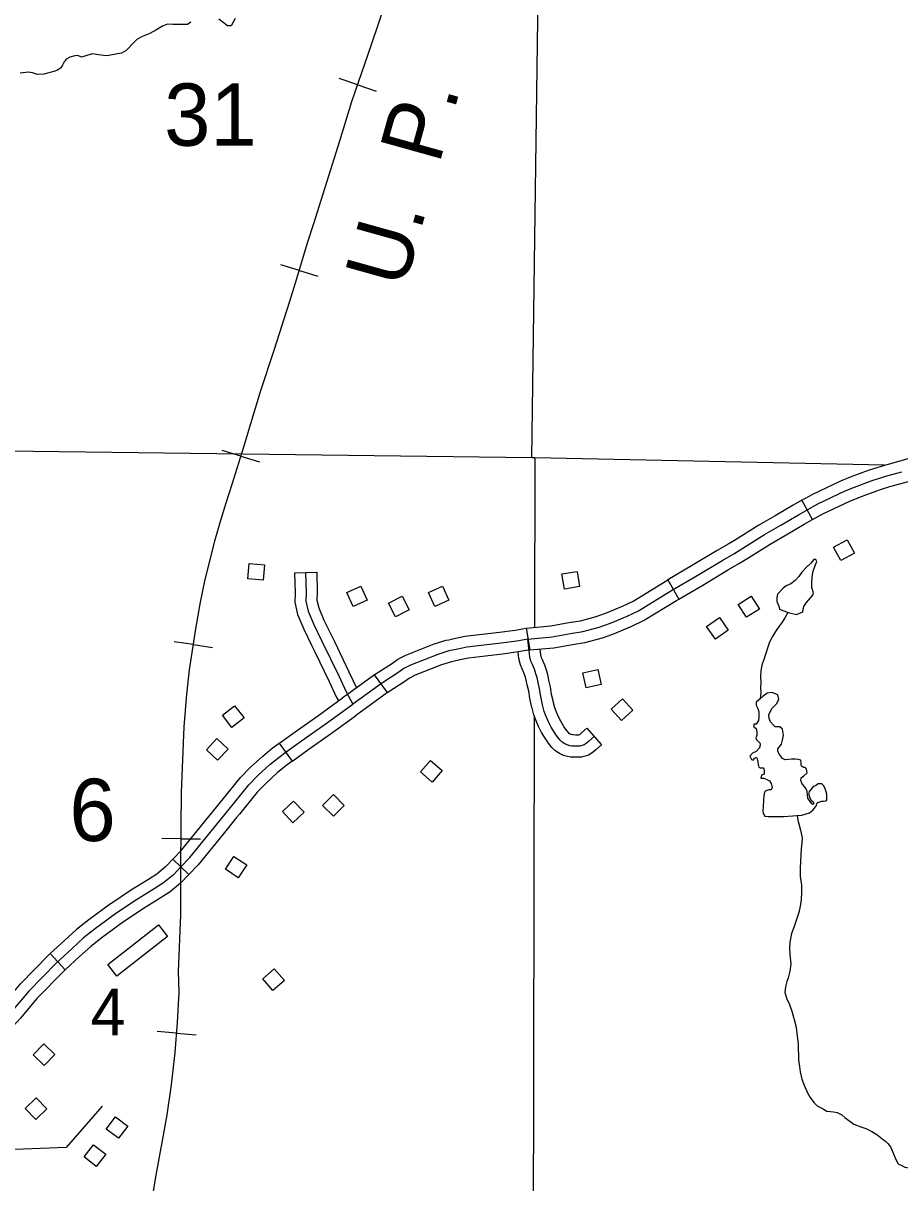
# Model space of a CAD drawing. Extents: x 61396 to 64680, y 55472 to 57605.
# Drawn here: x 62013.4 to 62199.2, y 56228.4 to 56474.2 of the extents above; entities that cross this region are included whole.
import ezdxf

# ---------------------------------------------------------------- set-up
doc = ezdxf.new("R2010")
doc.units = 0
for name, color, linetype in [('31', 7, 'Continuous'), ('35', 7, 'Continuous'), ('4', 7, 'Continuous'), ('40', 7, 'Continuous'), ('45', 7, 'Continuous'), ('5', 7, 'Continuous'), ('56', 7, 'Continuous')]:
    doc.layers.add(name, color=color, linetype=linetype)

msp = doc.modelspace()

# ---------------------------------------------------------------- linework, layer by layer
at = {"layer": '31'}
for p, q in [((62180.65, 56368.97), (62178.38, 56373.08)), ((62178.38, 56373.08), (62178.38, 56373.08)), ((62149.97, 56356.21), (62152.31, 56352.15)), ((62119.96, 56345.97), (62120.77, 56341.36)), ((62090.62, 56332.32), (62087.87, 56336.11)), ((62067.65, 56321.57), (62070.38, 56317.76)), ((62048.53, 56293.76), (62045.15, 56297)), ((62019.17, 56277.06), (62022.34, 56273.6))]:
    msp.add_line(p, q, dxfattribs=at)
for points in [[(62193.89, 56379.89), (62195.74, 56380.47), (62198.96, 56381.37), (62203.46, 56382.62), (62207.07, 56383.35), (62210.22, 56383.87)], [(62120.36, 56343.67), (62125.53, 56344.14), (62129.39, 56344.85), (62131.97, 56345.24), (62135.49, 56346.19), (62137.88, 56347.02), (62141.4, 56348.52), (62143.76, 56349.65), (62150.62, 56353.88), (62156.22, 56357.13), (62161.67, 56360.4), (62164, 56361.75), (62170.47, 56365.79), (62173.93, 56367.78), (62177.69, 56370.02), (62181.8, 56372.29), (62187.59, 56375.04), (62189.58, 56375.87), (62193.28, 56377.25), (62196.41, 56378.23), (62199.59, 56379.12)], [(62178.38, 56373.08), (62180.73, 56374.37), (62186.63, 56377.18), (62188.72, 56378.05), (62192.52, 56379.47), (62193.89, 56379.89)], [(62195.29, 56375.42), (62197.07, 56375.98), (62200.22, 56376.86), (62204.55, 56378.06), (62207.92, 56378.74), (62210.98, 56379.24)], [(62180.65, 56368.97), (62182.87, 56370.2), (62188.54, 56372.9), (62190.44, 56373.69), (62194.04, 56375.03), (62195.29, 56375.42)], [(62178.38, 56373.08), (62176.53, 56372.05), (62172.74, 56369.81), (62169.26, 56367.8), (62164.1, 56364.57)], [(62166.58, 56360.6), (62171.67, 56363.78), (62175.11, 56365.76), (62178.86, 56367.99), (62180.65, 56368.97)], [(62164.1, 56364.57), (62162.79, 56363.76), (62160.48, 56362.42), (62155.03, 56359.15), (62149.97, 56356.21)], [(62152.31, 56352.15), (62157.41, 56355.11), (62162.87, 56358.38), (62165.21, 56359.74), (62166.58, 56360.6)], [(62135.79, 56348.78), (62137.03, 56349.21), (62140.43, 56350.66), (62142.63, 56351.71), (62149.42, 56355.89), (62149.97, 56356.21)], [(62137.33, 56344.35), (62138.72, 56344.83), (62142.37, 56346.39), (62144.88, 56347.59), (62151.82, 56351.87), (62152.31, 56352.15)], [(62119.96, 56345.97), (62125.21, 56346.47), (62129, 56347.16), (62131.48, 56347.54), (62134.8, 56348.44), (62135.79, 56348.78)], [(62103.57, 56343.53), (62105.02, 56343.83), (62107.02, 56344.25), (62114.36, 56345.12), (62117.64, 56345.57), (62119.96, 56345.97)], [(62120.36, 56343.67), (62118, 56343.25), (62114.66, 56342.79), (62107.4, 56341.94), (62105.5, 56341.54), (62103.6, 56341.14), (62101.24, 56340.41), (62095.49, 56338.14), (62094.05, 56337.4), (62092.98, 56336.64), (62089.33, 56334.28), (62083.27, 56329.88)], [(62087.87, 56336.11), (62088, 56336.21), (62091.66, 56338.58), (62092.83, 56339.41), (62094.52, 56340.28), (62100.47, 56342.62), (62103.01, 56343.41), (62103.57, 56343.53)], [(62120.77, 56341.36), (62125.85, 56341.82), (62129.78, 56342.54), (62132.45, 56342.95), (62136.18, 56343.95), (62137.33, 56344.35)], [(62120.77, 56341.36), (62118.36, 56340.94), (62114.96, 56340.47), (62107.78, 56339.62), (62105.98, 56339.25), (62104.53, 56338.94)], [(62104.53, 56338.94), (62104.19, 56338.87), (62102.02, 56338.19), (62096.45, 56336), (62095.27, 56335.4), (62094.29, 56334.7), (62090.66, 56332.35), (62090.62, 56332.32)], [(62087.87, 56336.11), (62081.89, 56331.77), (62081.06, 56331.18)], [(62067.65, 56321.57), (62067.79, 56321.67), (62071.01, 56323.99), (62076.03, 56327.56), (62081.06, 56331.18)], [(62090.62, 56332.32), (62084.64, 56327.97), (62083.8, 56327.37)], [(62046.84, 56295.38), (62048.73, 56297.35), (62053.95, 56303.82), (62056.81, 56307.3), (62061.24, 56312.75), (62063.24, 56314.83), (62065.71, 56317.07), (62067.63, 56318.67), (62069.16, 56319.77), (62072.37, 56322.08), (62077.39, 56325.65), (62083.27, 56329.88)], [(62070.38, 56317.76), (62070.53, 56317.87), (62073.74, 56320.18), (62078.76, 56323.74), (62083.8, 56327.37)], [(62055.59, 56309.52), (62059.48, 56314.31), (62061.61, 56316.52), (62064.17, 56318.83), (62066.19, 56320.53), (62067.65, 56321.57)], [(62070.38, 56317.76), (62069.07, 56316.82), (62067.25, 56315.3), (62064.87, 56313.15), (62063, 56311.2), (62059.23, 56306.56)], [(62045.15, 56297), (62046.97, 56298.9), (62052.13, 56305.29), (62054.99, 56308.79), (62055.59, 56309.52)], [(62059.23, 56306.56), (62058.62, 56305.82), (62055.77, 56302.34), (62050.49, 56295.8), (62048.53, 56293.76)], [(62045.15, 56297), (62043.64, 56295.45), (62041.77, 56293.88), (62039.94, 56292.71), (62036.14, 56290.4), (62032.18, 56287.73)], [(62046.84, 56295.38), (62045.24, 56293.73), (62043.16, 56291.98), (62041.18, 56290.72), (62037.4, 56288.42), (62033.29, 56285.65), (62028.75, 56282.3), (62026.21, 56280.34), (62023.78, 56278.1), (62020.38, 56274.99), (62014.6, 56269.06), (62011.11, 56264.86), (62006.28, 56259.55), (62003.17, 56256.2), (62001.5, 56253.67), (61999.2, 56250.75), (61997.1, 56248.08), (61993.61, 56243.01), (61989.69, 56237.56), (61986.15, 56232.88), (61983.9, 56230.07)], [(62048.53, 56293.76), (62046.84, 56292.01), (62044.55, 56290.09), (62042.42, 56288.73), (62038.67, 56286.45), (62034.8, 56283.84)], [(62032.18, 56287.73), (62031.94, 56287.56), (62027.34, 56284.17), (62024.7, 56282.14), (62022.19, 56279.82), (62019.17, 56277.06)], [(62034.8, 56283.84), (62034.64, 56283.73), (62030.16, 56280.43), (62027.73, 56278.55), (62025.36, 56276.37), (62022.34, 56273.6)], [(62007.86, 56264.77), (62009.34, 56266.39), (62012.85, 56270.63), (62018.75, 56276.67), (62019.17, 56277.06)], [(62022.34, 56273.6), (62022.01, 56273.31), (62016.34, 56267.49), (62012.88, 56263.32), (62011.33, 56261.62)]]:
    msp.add_lwpolyline(points, dxfattribs=at)
at = {"layer": '35'}
for points in [[(62048.92, 56474.39), (62048.22, 56473.9), (62047.6, 56473.92), (62046.19, 56473.86), (62045.13, 56473.92), (62043.97, 56473.95), (62042.96, 56473.56), (62041.53, 56472.72), (62040.26, 56472), (62038.52, 56471.26), (62037.53, 56470.68), (62036.41, 56469.65), (62035.8, 56468.91), (62035.26, 56468.39), (62034.24, 56467.78), (62033.42, 56467.65), (62031.6, 56467.35), (62030.88, 56467.27), (62029.91, 56467.36), (62029.41, 56467.43), (62028.07, 56467.66), (62026.87, 56467.34), (62025.8, 56466.99), (62025.03, 56467.29), (62024.33, 56467.22), (62023.33, 56466.99), (62022.5, 56466.57), (62022.08, 56465.95), (62021.72, 56465.24), (62021.33, 56464.65), (62020.69, 56464.2), (62019.9, 56463.94), (62017.79, 56463.36), (62016.48, 56463.3), (62015.42, 56463.64), (62014.55, 56463.82), (62012.79, 56463.61)], [(62058.35, 56475.19), (62057.46, 56473.63), (62056.71, 56473.63), (62054.86, 56475.04)], [(62175.46, 56349.28), (62174.79, 56348.17), (62174.26, 56347.21), (62173.56, 56346.4), (62172.97, 56345.48), (62172.13, 56344.13), (62171.45, 56342.76), (62171.11, 56341.71), (62170.8, 56340.57), (62170.39, 56339.52), (62169.93, 56338.16), (62169.69, 56336.96), (62169.63, 56335.83), (62169.71, 56334.32), (62169.67, 56333.48), (62169.7, 56332.29), (62169.55, 56331.03)], [(62170.23, 56306.69), (62170.54, 56306.12), (62171.28, 56306.07), (62174.61, 56306.07), (62178.38, 56306.37), (62180.02, 56306.81), (62180.76, 56307.41), (62181.06, 56307.86), (62181.51, 56308.38), (62181.54, 56308.84), (62181.81, 56309.03), (62182.6, 56309.3), (62183, 56309.28), (62183.52, 56309.36), (62183.71, 56309.57), (62183.68, 56310.12), (62183.71, 56310.82), (62183.36, 56312.02), (62182.98, 56312.64), (62182.62, 56312.96), (62182.3, 56313.02), (62181.84, 56312.96), (62181.27, 56312.53), (62180.78, 56312.42), (62180.43, 56311.96), (62179.96, 56311.36), (62179.88, 56311.09), (62179.86, 56310.66), (62180.07, 56310.04), (62180.37, 56309.55), (62180.81, 56309.14), (62180.97, 56308.76), (62180.75, 56308.63), (62180.51, 56308.76), (62180.15, 56309.22), (62179.64, 56309.95), (62179.5, 56311.39), (62179.31, 56311.96), (62178.72, 56312.64), (62178.42, 56313.15), (62178.15, 56313.72), (62178.28, 56314.29), (62178.8, 56314.67), (62179.5, 56315.32), (62179.45, 56315.73), (62179.29, 56316.22), (62179.07, 56316.44), (62178.72, 56316.44), (62178.34, 56316.71), (62178.28, 56317), (62178.28, 56317.6), (62178.15, 56317.98), (62177.71, 56318.12), (62177.04, 56318.2), (62176.28, 56318.2), (62174.89, 56318.06), (62174.27, 56318.36), (62173.67, 56319.23), (62173.32, 56319.85), (62173.32, 56320.37), (62174.07, 56321.37), (62174.29, 56322.26), (62174.52, 56323.29), (62174.29, 56324.59), (62173.71, 56325.08), (62172.77, 56325.08), (62172.37, 56325.39), (62171.74, 56326.16), (62171.48, 56326.83), (62171.39, 56327.63), (62172.01, 56328.97), (62173, 56329.96), (62173.49, 56330.85), (62173.31, 56331.84), (62172.1, 56332.37), (62171.03, 56332.19), (62170.22, 56331.57), (62169.55, 56331.03), (62168.7, 56330.27), (62168.7, 56329.69), (62169.1, 56328.93), (62169.28, 56328.26), (62169.28, 56327.18), (62169.24, 56326.38), (62168.75, 56325.66), (62168.21, 56325.62), (62168.21, 56325.04), (62168.75, 56324.68), (62168.88, 56324.01), (62168.88, 56323.2), (62168.66, 56322.76), (62168.88, 56322.26), (62169.51, 56321.68), (62169.6, 56321.32), (62169.42, 56320.65), (62168.75, 56319.85), (62167.94, 56319.49), (62167.4, 56318.86), (62167.72, 56318.15), (62168.08, 56317.97), (62168.39, 56318.37)], [(62168.39, 56318.37), (62168.61, 56318.6), (62168.79, 56318.6), (62168.93, 56318.28), (62169.06, 56317.66), (62169.15, 56317.07), (62169.28, 56316.54), (62169.55, 56316.36), (62170.09, 56316.36), (62170.18, 56316.36), (62170.31, 56316.27), (62170.45, 56315.6), (62170.4, 56315.06), (62169.82, 56314.84), (62169.69, 56314.21), (62170.18, 56314.21), (62170.36, 56314.21), (62170.98, 56313.94), (62171.52, 56313.59), (62171.92, 56313.05), (62172.1, 56312.2), (62171.88, 56311.75), (62171.39, 56311.71), (62170.76, 56311.53), (62170.49, 56311.21), (62170.36, 56310.54), (62170.27, 56309.51), (62170.22, 56308.08), (62170.13, 56307.28), (62170.23, 56306.69)], [(62177.4, 56306.33), (62177.55, 56305.29), (62177.76, 56304.48), (62178.14, 56303.18), (62178.45, 56301.53), (62178.38, 56300.49), (62178.27, 56299.2), (62178.21, 56298.03), (62178.13, 56296.4), (62178.07, 56295.3), (62178.07, 56293.29), (62178.23, 56292.1), (62178.29, 56291.35), (62178.36, 56290.13), (62178.28, 56288.43), (62178.01, 56287.04), (62177.77, 56285.72), (62176.71, 56282.58), (62176.21, 56281.27), (62175.86, 56279.47), (62175.78, 56278.09), (62175.85, 56276.84), (62176.03, 56274.87), (62175.86, 56273.32), (62175.5, 56271.9), (62175.24, 56271.08), (62174.9, 56270), (62174.81, 56268.74), (62175.23, 56267.43), (62175.77, 56266.26), (62176.28, 56264.83), (62176.74, 56263.03), (62177.17, 56261.44), (62177.33, 56260.13), (62177.59, 56257.81), (62177.72, 56254.46), (62177.89, 56253.08), (62178.05, 56251.93), (62178.38, 56250.4), (62178.86, 56249.13), (62179.6, 56247.52), (62180.16, 56246.53), (62180.97, 56245.49), (62181.65, 56244.76), (62182.36, 56244.38), (62182.99, 56244.02), (62183.66, 56243.66), (62184.45, 56243.59), (62185.11, 56243.52), (62185.86, 56243.33), (62186.88, 56242.83), (62187.49, 56242.31), (62189.38, 56240.9), (62190.87, 56240.32), (62191.95, 56239.94), (62193.22, 56239.32), (62194.28, 56238.67), (62195.01, 56238.13), (62195.69, 56237.55), (62196.13, 56237.28), (62196.65, 56236.8), (62197.17, 56236.09)], [(62197.17, 56236.09), (62197.64, 56235.07), (62197.98, 56234.23), (62198.32, 56233.37), (62198.82, 56232.5), (62199.61, 56232.12), (62200.19, 56231.73), (62202.77, 56231.31), (62205.28, 56231.05), (62206.92, 56230.94), (62207.9, 56230.6), (62208.72, 56230.18), (62209.87, 56229.53), (62211.68, 56228.52)]]:
    msp.add_lwpolyline(points, dxfattribs=at)
msp.add_lwpolyline([(62173.68, 56350.03), (62175.48, 56349.3), (62177.24, 56348.89), (62178.64, 56349.41), (62178.68, 56349.96), (62178.79, 56350.55), (62179.41, 56351.39), (62179.89, 56351.98), (62180.7, 56352.94), (62180.85, 56353.49), (62180.48, 56354.56), (62180.48, 56355.4), (62180.59, 56356.84), (62180.77, 56358.05), (62181.14, 56359.04), (62181.55, 56360.07), (62181.36, 56360.51), (62180.96, 56360.51), (62180.3, 56359.78), (62179.3, 56358.82), (62178.38, 56357.83), (62177.79, 56356.95), (62176.95, 56356.06), (62176.07, 56355.36), (62175.11, 56354.92), (62174.41, 56354.44), (62173.27, 56353.16), (62173.09, 56352.39), (62173.09, 56351.65), (62173.49, 56350.62)], close=True, dxfattribs=at)
at = {"layer": '4'}
msp.add_lwpolyline([(62195.89, 56380.52), (62121.79, 56382.05), (62121.21, 56382.06), (62004.31, 56383.53)], dxfattribs=at)
at = {"layer": '40'}
for p, q in [((62084.3, 56461.11), (62080.4, 56462.46)), ((62084.3, 56461.11), (62088.2, 56459.76)), ((62071.93, 56421.76), (62067.98, 56422.96)), ((62071.93, 56421.76), (62075.88, 56420.57)), ((62059.52, 56382.42), (62055.58, 56383.64)), ((62059.52, 56382.42), (62063.47, 56381.21)), ((62049.47, 56342.48), (62045.4, 56343.11)), ((62049.47, 56342.48), (62053.55, 56341.85)), ((62046.89, 56301.36), (62042.76, 56301.39)), ((62046.89, 56301.36), (62051.01, 56301.33)), ((62045.93, 56260.14), (62041.82, 56260.49)), ((62045.93, 56260.14), (62050.04, 56259.79))]:
    msp.add_line(p, q, dxfattribs=at)
for points in [[(62038.9, 56213.42), (62041.42, 56229.26), (62043.17, 56238.53), (62043.91, 56242.84), (62044.85, 56249.23), (62045.59, 56256.08), (62046.13, 56262.41), (62046.46, 56268.86), (62046.33, 56273.23), (62046.8, 56285.2), (62046.84, 56295.38), (62046.9, 56303.85), (62046.99, 56311.16), (62047.51, 56325.08), (62048.08, 56331.98), (62048.65, 56337.17), (62049.99, 56345.82), (62050.96, 56351.46), (62051.9, 56355.92), (62054.05, 56364.49), (62055.27, 56368.87), (62056.4, 56372.52), (62057.7, 56376.5), (62060.14, 56384.41), (62062.33, 56391.68), (62063.67, 56396.14), (62066.63, 56404.87), (62069.88, 56415.26), (62071.42, 56420.09), (62073.69, 56427.6), (62075.03, 56431.7), (62076.54, 56436.65), (62080.51, 56449.23), (62083.07, 56457.55), (62087.25, 56469.64), (62090.34, 56478.86)], [(62046.84, 56295.38), (62046.9, 56303.85), (62046.99, 56311.16), (62047.51, 56325.08), (62048.08, 56331.98), (62048.65, 56337.17), (62049.99, 56345.82), (62050.96, 56351.46), (62051.9, 56355.92), (62054.05, 56364.49), (62055.27, 56368.87), (62056.4, 56372.52), (62057.7, 56376.5), (62060.14, 56384.41), (62062.33, 56391.68), (62063.67, 56396.14), (62066.63, 56404.87), (62069.88, 56415.26), (62071.42, 56420.09), (62073.69, 56427.6), (62075.03, 56431.7), (62076.54, 56436.65), (62080.51, 56449.23), (62083.07, 56457.55), (62087.25, 56469.64), (62090.34, 56478.86)], [(62034.81, 56178.43), (62035.06, 56186.09), (62035.33, 56193.38), (62035.8, 56199.64), (62036.98, 56206.19), (62038.9, 56213.42), (62041.42, 56229.26), (62043.17, 56238.53), (62043.91, 56242.84), (62044.85, 56249.23), (62045.59, 56256.08), (62046.13, 56262.41), (62046.46, 56268.86), (62046.33, 56273.23), (62046.8, 56285.2), (62046.84, 56295.38)]]:
    msp.add_lwpolyline(points, dxfattribs=at)
at = {"layer": '45'}
for p, q in [((62070.91, 56357.73), (62075.6, 56357.86)), ((62132.84, 56324.75), (62135.92, 56321.22))]:
    msp.add_line(p, q, dxfattribs=at)
for points in [[(62070.91, 56357.73), (62071.03, 56353.44), (62070.97, 56351.46), (62071.56, 56348.84), (62072.88, 56345.74), (62074.54, 56342.37), (62075.15, 56341.1)], [(62073.26, 56357.79), (62073.38, 56353.44), (62073.32, 56351.68), (62073.8, 56349.56), (62075.01, 56346.72), (62076.65, 56343.39), (62080.34, 56335.71), (62081.85, 56332.5), (62083.27, 56329.88)], [(62075.6, 56357.86), (62075.72, 56353.43), (62075.67, 56351.91), (62076.04, 56350.29), (62077.14, 56347.7), (62078.75, 56344.42), (62079.37, 56343.13)], [(62134.38, 56322.99), (62133.21, 56321.96), (62132.73, 56321.53), (62132.25, 56321.22), (62131.37, 56320.99), (62130.38, 56320.97), (62129.65, 56321), (62129.25, 56321.07), (62128.68, 56321.23), (62128.16, 56321.45), (62127.59, 56321.85), (62127.19, 56322.26), (62126.58, 56322.99), (62125.98, 56323.88), (62125.32, 56325.02), (62124.73, 56326.14), (62124.26, 56327.25), (62123.83, 56328.32), (62123.47, 56329.73), (62123.09, 56331.5), (62122.82, 56333.1), (62122.51, 56334.46), (62122.3, 56335.55), (62122.05, 56336.32), (62121.72, 56337.32), (62121.3, 56338.29), (62120.99, 56338.95), (62120.77, 56339.91), (62120.36, 56343.67)], [(62075.15, 56341.1), (62078.22, 56334.7), (62079.76, 56331.44), (62080.23, 56330.58)], [(62079.37, 56343.13), (62082.45, 56336.71), (62084.05, 56333.34)], [(62125.78, 56330.17), (62125.75, 56330.27), (62125.39, 56331.94), (62125.12, 56333.56), (62124.8, 56334.95), (62124.57, 56336.13), (62124.28, 56337.05), (62123.91, 56338.14), (62123.44, 56339.25), (62123.22, 56339.72), (62123.09, 56340.3), (62122.95, 56341.55)], [(62121.24, 56328.99), (62121.19, 56329.19), (62120.79, 56331.06), (62120.52, 56332.65), (62120.22, 56333.96), (62120.02, 56334.96), (62119.82, 56335.6), (62119.52, 56336.49), (62119.17, 56337.33), (62118.76, 56338.18), (62118.46, 56339.53), (62118.31, 56340.93)], [(62135.92, 56321.22), (62134.76, 56320.21), (62134.16, 56319.67), (62133.21, 56319.05), (62131.69, 56318.65), (62130.35, 56318.63), (62129.4, 56318.67), (62128.74, 56318.78), (62127.9, 56319.02), (62127.04, 56319.38), (62126.06, 56320.05), (62125.44, 56320.69), (62124.7, 56321.58), (62123.99, 56322.64), (62123.27, 56323.88), (62122.6, 56325.14), (62122.09, 56326.36), (62121.6, 56327.59), (62121.24, 56328.99)], [(62132.84, 56324.75), (62131.65, 56323.72), (62131.29, 56323.4), (62131.28, 56323.39), (62131.05, 56323.33), (62130.41, 56323.31), (62129.9, 56323.34), (62129.77, 56323.36), (62129.45, 56323.45), (62129.29, 56323.52), (62129.11, 56323.64), (62128.93, 56323.83), (62128.45, 56324.4), (62127.97, 56325.12), (62127.37, 56326.16), (62126.85, 56327.15), (62126.43, 56328.14), (62126.06, 56329.06), (62125.78, 56330.17)]]:
    msp.add_lwpolyline(points, dxfattribs=at)
at = {"layer": '5'}
for points in [[(62121.21, 56382.06), (62123.47, 56547.31)], [(62121.79, 56382.05), (62121.72, 56346.14)], [(62121.69, 56327.37), (62121.49, 56216.01)]]:
    msp.add_lwpolyline(points, dxfattribs=at)
at = {"layer": '56'}
for points in [[(62186.67, 56360.3), (62185.11, 56363.16), (62187.98, 56364.72), (62189.53, 56361.87)], [(62061.03, 56356.43), (62061.32, 56359.67), (62064.57, 56359.37), (62064.28, 56356.14)], [(62128.08, 56354.26), (62127.54, 56357.47), (62130.76, 56358.01), (62131.29, 56354.8)], [(62083.36, 56350.53), (62082.02, 56353.5), (62084.99, 56354.84), (62086.33, 56351.88)], [(62100.61, 56350.57), (62099.29, 56353.54), (62102.27, 56354.87), (62103.59, 56351.89)], [(62092.29, 56348.37), (62090.83, 56351.28), (62093.75, 56352.74), (62095.21, 56349.83)], [(62166.69, 56348.27), (62164.94, 56351.01), (62167.69, 56352.77), (62169.44, 56350.02)], [(62160.07, 56343.67), (62158.23, 56346.35), (62160.92, 56348.2), (62162.76, 56345.52)], [(62132.72, 56333.36), (62132.02, 56336.54), (62135.2, 56337.24), (62135.91, 56334.07)], [(62057.64, 56324.95), (62055.65, 56327.52), (62058.22, 56329.52), (62060.22, 56326.96)], [(62138, 56328.78), (62140.39, 56330.99), (62142.6, 56328.59), (62140.21, 56326.38)], [(62054.61, 56317.97), (62052.23, 56320.19), (62054.46, 56322.57), (62056.84, 56320.35)], [(62097.57, 56315.5), (62099.7, 56317.96), (62102.16, 56315.83), (62100.04, 56313.36)], [(62068.35, 56307.11), (62070.72, 56309.33), (62072.95, 56306.95), (62070.58, 56304.73)], [(62076.86, 56308.42), (62079.16, 56310.72), (62081.46, 56308.42), (62079.16, 56306.12)], [(62056.28, 56294.9), (62058.08, 56297.61), (62060.8, 56295.8), (62059, 56293.09)], [(62033.24, 56272.24), (62031.32, 56274.7), (62042.1, 56283.11), (62044.03, 56280.64)], [(62064.16, 56271.64), (62066.6, 56273.79), (62068.76, 56271.34), (62066.31, 56269.19)], [(62017.87, 56253.3), (62015.54, 56255.57), (62017.82, 56257.9), (62020.15, 56255.63)], [(62013.81, 56244.22), (62016.15, 56246.47), (62018.41, 56244.12), (62016.07, 56241.87)], [(62033.62, 56237.87), (62031.03, 56239.84), (62033.01, 56242.43), (62035.6, 56240.46)], [(62028.87, 56231.92), (62026.32, 56233.95), (62028.35, 56236.5), (62030.9, 56234.48)]]:
    msp.add_lwpolyline(points, close=True, dxfattribs=at)
for points in [[(62030.17, 56244.71), (62022.49, 56235.96)], [(62022.49, 56235.96), (62002.57, 56235.15)]]:
    msp.add_lwpolyline(points, dxfattribs=at)

# ---------------------------------------------------------------- texts
at = {"layer": '40'}
msp.add_text('U.  P.', height=13.2, rotation=74.4049, dxfattribs=at).set_placement((62094.16, 56417.62))
at = {"layer": '5'}
for s, p in [('31', (62043.28, 56448.2)), ('6', (62023.21, 56300.87))]:
    msp.add_text(s, height=13.2, dxfattribs=at).set_placement(p)
at = {"layer": '56'}
msp.add_text('4', height=9.9, dxfattribs=at).set_placement((62027.71, 56259.68))

doc.saveas('drawing.dxf')
